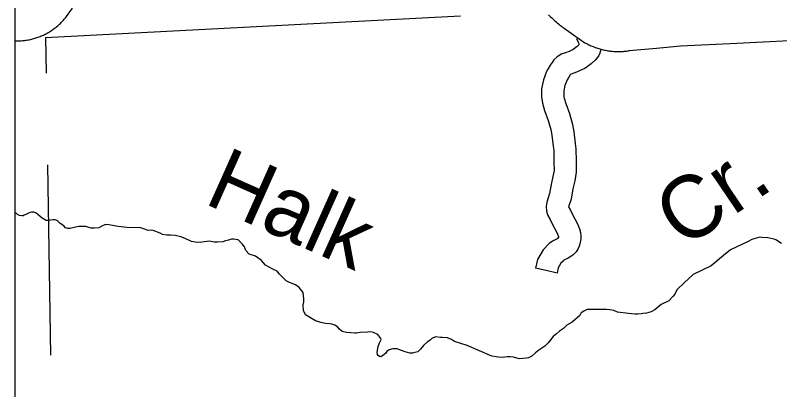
# Model space of a CAD drawing. Extents: x 1720274 to 1751788, y 372074 to 391887.
# Drawn here: x 1729991 to 1730808, y 379181 to 379582 of the extents above; entities that cross this region are included whole.
import ezdxf

# ---------------------------------------------------------------- set-up
doc = ezdxf.new("R2010")
doc.units = 0
for name, color, linetype in [('Level 10', 7, 'Continuous'), ('Level 35', 7, 'Continuous'), ('Level 46', 7, 'Continuous'), ('Level 5', 7, 'Continuous'), ('R_Draft', 7, 'Continuous')]:
    doc.layers.add(name, color=color, linetype=linetype)

msp = doc.modelspace()

# ---------------------------------------------------------------- linework, layer by layer
at = {"layer": 'Level 10'}
for points in [[(1729990.7, 379554.19), (1729990.91, 379554.18), (1729992.14, 379554.16), (1729993.37, 379554.16), (1729994.6, 379554.18), (1729995.83, 379554.23), (1729997.06, 379554.3), (1729998.29, 379554.39), (1729999.51, 379554.51), (1730000.74, 379554.65), (1730001.95, 379554.81), (1730003.17, 379554.99), (1730004.38, 379555.2), (1730005.59, 379555.43), (1730006.8, 379555.68), (1730007.99, 379555.95), (1730009.19, 379556.25), (1730010.38, 379556.56), (1730011.56, 379556.9), (1730012.74, 379557.27), (1730013.9, 379557.65), (1730015.07, 379558.05), (1730016.22, 379558.48), (1730017.37, 379558.93), (1730018.51, 379559.4), (1730019.63, 379559.89), (1730020.75, 379560.4), (1730021.86, 379560.93), (1730022.96, 379561.48), (1730024.05, 379562.05), (1730025.13, 379562.64), (1730026.2, 379563.26), (1730027.25, 379563.89), (1730028.29, 379564.54), (1730029.33, 379565.21), (1730030.35, 379565.9), (1730031.35, 379566.61), (1730032.35, 379567.33), (1730033.32, 379568.08), (1730034.29, 379568.84), (1730035.24, 379569.62), (1730036.18, 379570.42), (1730037.1, 379571.23), (1730038.01, 379572.06), (1730038.9, 379572.91), (1730039.77, 379573.78), (1730040.63, 379574.66), (1730041.47, 379575.56), (1730042.3, 379576.47), (1730043.11, 379577.4), (1730043.9, 379578.34), (1730044.67, 379579.29), (1730045.48, 379580.34), (1730052.01, 379589.22)], [(1730560.77, 379582.09), (1730562.99, 379579.87), (1730564.17, 379578.74), (1730565.31, 379577.66), (1730566.47, 379576.59), (1730567.63, 379575.54), (1730568.82, 379574.5), (1730570.01, 379573.48), (1730571.22, 379572.47), (1730572.43, 379571.47), (1730573.66, 379570.49), (1730574.9, 379569.53), (1730576.15, 379568.57), (1730577.42, 379567.64), (1730578.69, 379566.71), (1730579.95, 379565.82), (1730587.4, 379560.67)], [(1730587.4, 379560.67), (1730599.64, 379552.21), (1730601.55, 379551.17), (1730602.67, 379550.59), (1730603.8, 379550.04), (1730604.94, 379549.5), (1730606.08, 379548.98), (1730607.24, 379548.48), (1730608.4, 379548), (1730609.73, 379547.48)], [(1730609.73, 379547.48), (1730610.75, 379547.1), (1730611.94, 379546.68), (1730613.13, 379546.28), (1730614.33, 379545.91), (1730615.54, 379545.55), (1730616.75, 379545.22), (1730617.97, 379544.9), (1730619.2, 379544.61), (1730620.42, 379544.34), (1730621.66, 379544.09), (1730622.89, 379543.86), (1730624.13, 379543.65), (1730625.38, 379543.47), (1730626.63, 379543.31), (1730627.88, 379543.16), (1730629.13, 379543.04), (1730630.38, 379542.94), (1730631.64, 379542.87), (1730632.9, 379542.81), (1730634.15, 379542.78), (1730635.41, 379542.77), (1730636.67, 379542.78), (1730637.93, 379542.81), (1730639.19, 379542.87), (1730640.44, 379542.94), (1730641.7, 379543.04), (1730642.95, 379543.16), (1730644.2, 379543.3), (1730645.45, 379543.46), (1730646.69, 379543.65), (1730647.06, 379543.71), (1730676.11, 379546.4), (1730701.96, 379548.81), (1730724.08, 379549.88), (1730754.76, 379551.22), (1730790.19, 379553.12), (1730818.43, 379554.58)]]:
    msp.add_lwpolyline(points, dxfattribs=at)
at = {"layer": 'Level 35'}
for points in [[(1730066.09, 379355.45), (1730063.33, 379355.7), (1730058.8, 379355.7), (1730053.78, 379354.44), (1730049.26, 379353.44), (1730046.74, 379353.44), (1730044.48, 379354.19), (1730042.47, 379356.21), (1730038.7, 379358.72), (1730036.19, 379361.24), (1730035.18, 379361.99), (1730033.43, 379362.75), (1730030.66, 379362.75), (1730028.65, 379362.24), (1730025.64, 379361.99), (1730023.88, 379361.99), (1730019.32, 379364.68), (1730017.15, 379366.16), (1730014.8, 379368.6), (1730013.05, 379369.99), (1730010.7, 379370.78), (1730008.18, 379370.95), (1730005.48, 379370.17), (1730002.69, 379368.69), (1730000.17, 379367.64), (1729998.95, 379367.12), (1729997.56, 379367.2), (1729995.3, 379367.38), (1729993.22, 379368.53), (1729991.71, 379369.79), (1729990.7, 379370.39)], [(1730400.54, 379223.89), (1730399.03, 379224.64), (1730396.77, 379224.9), (1730394.26, 379224.9), (1730390.23, 379223.64), (1730387.72, 379221.88), (1730386.72, 379220.12), (1730384.96, 379218.86), (1730381.44, 379216.09), (1730379.93, 379216.59), (1730378.68, 379217.6), (1730377.92, 379218.61), (1730377.42, 379221.12), (1730378.68, 379227.41), (1730380.18, 379231.18), (1730381.69, 379234.71), (1730381.44, 379235.96), (1730378.11, 379240.14), (1730373.61, 379242.19), (1730370.89, 379242.8), (1730367.27, 379242.6), (1730359.3, 379242.19), (1730355.56, 379241.5), (1730353.55, 379241.5), (1730349.49, 379241.78), (1730344.59, 379242.19), (1730340.09, 379243.41), (1730337.23, 379245.87), (1730334.98, 379248.32), (1730332.32, 379249.96), (1730329.25, 379251.19), (1730326.6, 379251.39), (1730322.3, 379252.01), (1730317.4, 379253.03), (1730311.68, 379254.87), (1730304.52, 379259.17), (1730301.05, 379261.01), (1730298.8, 379265.92), (1730298.59, 379271.44), (1730299.21, 379274.72), (1730299, 379278.4), (1730298.39, 379284.94), (1730294.1, 379290.26), (1730290.21, 379293.33), (1730283.88, 379295.58), (1730280.2, 379297.63), (1730273.04, 379304.79), (1730270.59, 379307.86), (1730265.89, 379310.11), (1730258.32, 379314.4), (1730254.03, 379319.11), (1730247.49, 379323.81), (1730240.74, 379325.86), (1730237.07, 379329.95), (1730235.84, 379334.04), (1730233.18, 379337.11), (1730229.09, 379341.2), (1730223.98, 379342.23), (1730221.94, 379342.02), (1730218.67, 379341), (1730215.4, 379340.18), (1730212.73, 379339.1), (1730207.01, 379338.69), (1730203.75, 379338.75), (1730198.02, 379339.77), (1730190.05, 379338.75), (1730185.15, 379338.55), (1730179.01, 379339.57), (1730172.27, 379342.64), (1730167.57, 379344.68), (1730161.43, 379345.91), (1730156.53, 379346.32), (1730152.85, 379346.52), (1730148.01, 379347.15), (1730145.75, 379348.41), (1730137.93, 379351.23), (1730135.88, 379351.64), (1730132.82, 379351.43), (1730124.84, 379354.3), (1730109.81, 379354.44), (1730100.77, 379355.7), (1730090.72, 379357.46), (1730087.2, 379357.71), (1730083.18, 379355.95), (1730080.16, 379354.19), (1730075.39, 379353.94), (1730071.87, 379353.94), (1730066.09, 379355.45)], [(1730809.86, 379337.34), (1730803.58, 379341.36), (1730801.82, 379342.12), (1730795.29, 379343.38), (1730788.77, 379343.86), (1730786.52, 379344.07), (1730781.47, 379342.87), (1730778.2, 379341.62), (1730774.18, 379339.6), (1730755.34, 379330.55), (1730747.8, 379324.51), (1730734.48, 379313.69), (1730715.38, 379304.13), (1730705.84, 379295.33), (1730697.79, 379288.03), (1730695.76, 379283.31), (1730693.72, 379280.85), (1730689.42, 379276.15), (1730681.04, 379272.06), (1730674.3, 379266.53), (1730670.41, 379264.49), (1730665.3, 379262.85), (1730661.61, 379262.63), (1730659.85, 379262.38), (1730656.33, 379261.87), (1730653.32, 379261.87), (1730649.3, 379262.12), (1730646.28, 379262.63), (1730634.47, 379264.14), (1730630.45, 379265.9), (1730626.43, 379266.65), (1730622.66, 379266.9), (1730617.39, 379266.9), (1730611.36, 379266.9), (1730606.58, 379266.9), (1730602.06, 379266.9), (1730598.29, 379265.14), (1730595.78, 379263.13), (1730594.27, 379260.36), (1730585.98, 379253.32), (1730580.45, 379250.05), (1730576.68, 379246.53), (1730572.41, 379243.51), (1730569.14, 379240.99), (1730565.62, 379237.98), (1730560.35, 379231.18), (1730556.83, 379227.66), (1730550.3, 379223.39), (1730546.78, 379220.37), (1730542.76, 379217.1), (1730539.24, 379215.08), (1730537.23, 379214.83), (1730529.19, 379214.08), (1730523.41, 379215.84), (1730519.64, 379216.34), (1730516.37, 379216.34), (1730511.6, 379215.34), (1730507.08, 379215.84), (1730500.29, 379216.85), (1730473.66, 379228.42), (1730460.09, 379232.69), (1730457.07, 379234.71), (1730452.55, 379236.47), (1730447.02, 379236.97), (1730445.26, 379236.97), (1730439.74, 379237.47), (1730435.97, 379235.96), (1730434.21, 379234.2), (1730431.19, 379232.19), (1730426.92, 379228.42), (1730423.91, 379224.39), (1730420.89, 379221.62), (1730417.88, 379220.87), (1730415.36, 379220.12), (1730412.35, 379220.12), (1730407.57, 379221.62), (1730400.54, 379223.89)]]:
    msp.add_lwpolyline(points, dxfattribs=at)
at = {"layer": 'Level 46'}
for points in [[(1730590.58, 379556.79), (1730592.81, 379552.23), (1730593.13, 379551.44), (1730593.21, 379549.98), (1730593.21, 379549.87), (1730591.3, 379548.07), (1730587.01, 379545.04), (1730584.04, 379543.48), (1730582.81, 379542.88), (1730578.7, 379541.51), (1730575.09, 379540.18), (1730572.16, 379538.68), (1730569.73, 379536.85), (1730566.46, 379533.86), (1730564.54, 379531.16), (1730562.41, 379528.01), (1730560.01, 379524.06), (1730558.24, 379520.67), (1730556.61, 379516.47), (1730555.21, 379512.44), (1730553.37, 379502.81), (1730553.37, 379494.48)], [(1730616.73, 379545.16), (1730616.42, 379543.38), (1730615.53, 379540.98), (1730614.42, 379538.6), (1730612.84, 379536.14), (1730610.57, 379533.66), (1730606.34, 379529.68), (1730599.41, 379524.77), (1730594.7, 379522.31), (1730591.75, 379520.88), (1730586.55, 379519.15), (1730584.76, 379518.49), (1730584.34, 379518.1), (1730584.02, 379517.66), (1730582.36, 379515.21), (1730580.66, 379512.4), (1730579.85, 379510.86), (1730578.86, 379508.29), (1730578.16, 379506.3), (1730577.07, 379500.58), (1730577.07, 379494.48)], [(1730553.37, 379494.48), (1730554.35, 379487.59), (1730556.59, 379479.73), (1730560.45, 379469.11), (1730563.21, 379459.28), (1730564.38, 379453.23), (1730565.79, 379441.71), (1730566.26, 379437.15), (1730566.48, 379424.84), (1730566.58, 379415.56), (1730565.46, 379409.07), (1730563.58, 379400.53), (1730561.79, 379390.82), (1730558.82, 379381.68), (1730558.13, 379377.09), (1730558.57, 379372.05), (1730559.28, 379369.49), (1730560.14, 379367.38), (1730562.62, 379362.95), (1730564.65, 379358.57), (1730570.13, 379348.38), (1730571.19, 379345.68), (1730571.48, 379344.54), (1730571.52, 379344.3), (1730571.4, 379343.34), (1730569.88, 379342.4), (1730565.08, 379339.87), (1730561.24, 379337.33), (1730554.86, 379330.59), (1730548.88, 379320.15), (1730546.81, 379311.07)], [(1730577.07, 379494.48), (1730577.51, 379492.78), (1730579.15, 379487.04), (1730583.02, 379476.38), (1730586.29, 379464.74), (1730587.8, 379456.93), (1730589.34, 379444.37), (1730589.94, 379438.58), (1730590.17, 379425.18), (1730590.3, 379413.67), (1730588.73, 379404.51), (1730586.81, 379395.83), (1730584.81, 379384.98), (1730582.11, 379376.65), (1730583.75, 379373.71), (1730585.85, 379369.17), (1730591.67, 379358.36), (1730593.77, 379353.01), (1730594.77, 379349.15), (1730595.27, 379345.54), (1730595.19, 379342.6), (1730594.66, 379338.37), (1730593.55, 379334.65), (1730592.57, 379332.15), (1730590.43, 379328.58), (1730586.73, 379324.97), (1730581.68, 379321.83), (1730577.17, 379319.45), (1730576.58, 379319.06), (1730574.01, 379316.35), (1730571.2, 379311.44), (1730569.92, 379305.8), (1730558.36, 379308.44), (1730546.81, 379311.07)]]:
    msp.add_lwpolyline(points, dxfattribs=at)
at = {"layer": 'Level 5'}
for points in [[(1730023.1, 379557.93), (1730466.57, 379580.79)], [(1730023.1, 379557.93), (1730023.68, 379519.52)], [(1730025.15, 379421.64), (1730028.22, 379218.12)]]:
    msp.add_lwpolyline(points, dxfattribs=at)
at = {"layer": 'R_Draft'}
msp.add_lwpolyline([(1729990.7, 381816.11), (1741847.55, 381816.11), (1741847.55, 374371.32), (1729990.7, 374371.32)], close=True, dxfattribs=at)

# ---------------------------------------------------------------- texts
at = {"layer": 'Level 35'}
for s, rotation, p in [('Halk', 335.90816, (1730191.05, 379380.9)), ('Cr.', 34.05281, (1730704.58, 379330.61))]:
    msp.add_text(s, height=66.739, rotation=rotation, dxfattribs=at).set_placement(p)

doc.saveas('drawing.dxf')
